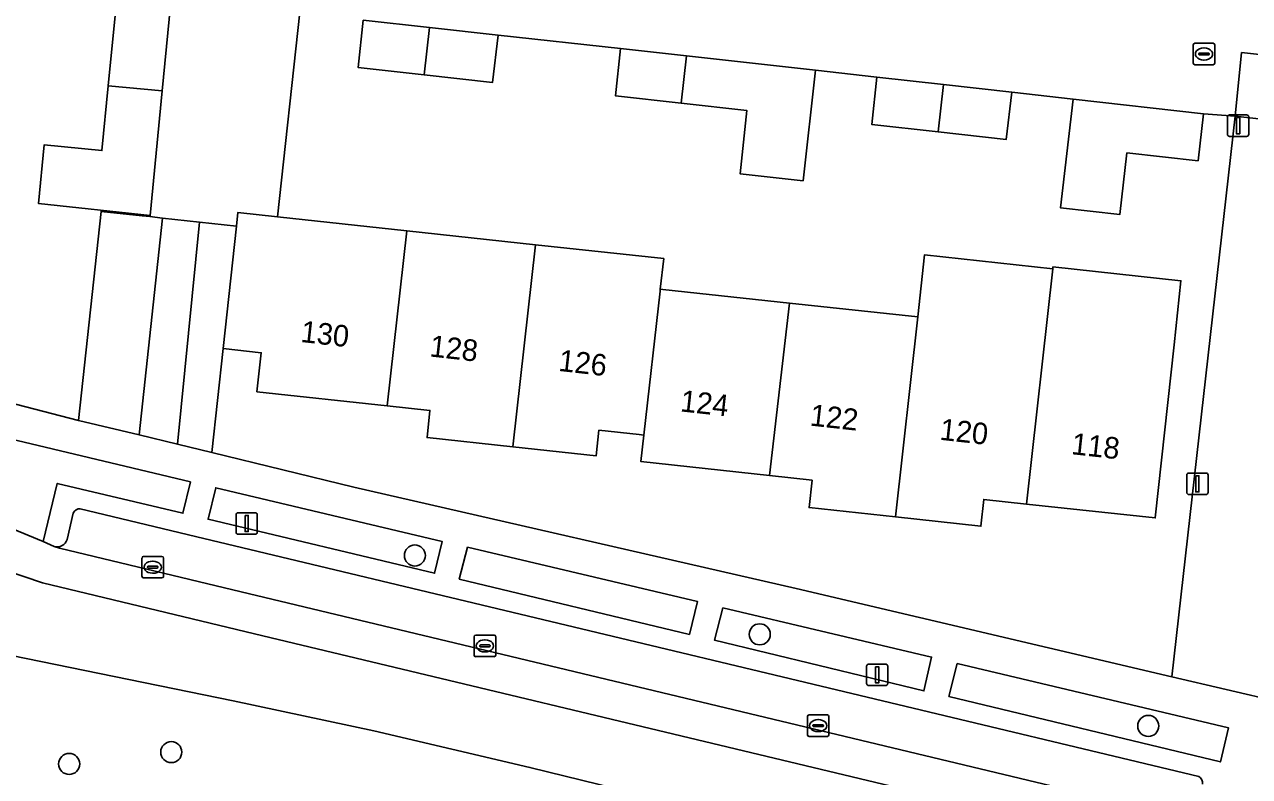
# Model space of a CAD drawing. Extents: x 162026 to 163502, y 387295 to 388169.
# Drawn here: x 162389.2 to 162446.1, y 387393.2 to 387428.2 of the extents above; entities that cross this region are included whole.
import ezdxf

# ---------------------------------------------------------------- set-up
doc = ezdxf.new("R2010")
doc.units = 0
for name, color, linetype in [('IMGEO_Berm_groen', 7, 'Continuous'), ('IMGEO_Boom', 7, 'Continuous'), ('IMGEO_Erf', 7, 'Continuous'), ('IMGEO_Groenvoorziening', 7, 'Continuous'), ('IMGEO_Kolk', 7, 'Continuous'), ('IMGEO_Lichtmast', 7, 'Continuous'), ('IMGEO_Muur', 7, 'Continuous'), ('IMGEO_Pand', 7, 'Continuous'), ('IMGEO_Pand_nummerreeks', 7, 'Continuous'), ('IMGEO_Parkeervlak_open', 7, 'Continuous'), ('IMGEO_Rijbaan_lokaal_gesloten', 7, 'Continuous'), ('IMGEO_Rijbaan_lokaal_open', 7, 'Continuous'), ('IMGEO_Voetpad_open', 7, 'Continuous')]:
    doc.layers.add(name, color=color, linetype=linetype)

msp = doc.modelspace()

# ---------------------------------------------------------------- linework, layer by layer
at = {"layer": 'IMGEO_Berm_groen'}
msp.add_lwpolyline([(162425.53, 387390.413), (162418.248, 387392.291), (162412.634, 387393.669), (162405.374, 387395.373), (162398.853, 387396.753), (162376.793, 387401.271)], dxfattribs=at)
at = {"layer": 'IMGEO_Boom'}
for centre in [(162407.286, 387403.51), (162423.306, 387399.849), (162441.353, 387395.594), (162395.972, 387394.379), (162391.229, 387393.829)]:
    msp.add_circle(centre, 0.489, dxfattribs=at)
at = {"layer": 'IMGEO_Erf'}
for points in [[(162386.331, 387411.152), (162391.662, 387409.78), (162392.713, 387419.492), (162394.616, 387419.286), (162394.98, 387419.247), (162394.985, 387419.298), (162389.801, 387419.859), (162390.065, 387422.578), (162392.75, 387422.317), (162393.042, 387425.325), (162393.359, 387428.586)], [(162401.939, 387428.743), (162400.911, 387419.241), (162406.912, 387418.59), (162412.884, 387417.942), (162418.844, 387417.296), (162418.685, 387415.884), (162418.808, 387415.871), (162424.683, 387415.234), (162430.645, 387414.587), (162430.965, 387417.474), (162436.918, 387416.828), (162436.927, 387416.912), (162442.872, 387416.267), (162442.549, 387413.295), (162441.676, 387405.253), (162435.704, 387405.901), (162433.715, 387406.117), (162433.58, 387404.87), (162429.615, 387405.3), (162425.601, 387405.735), (162425.739, 387407.005), (162423.767, 387407.219), (162417.783, 387407.869), (162417.922, 387409.102), (162417.71, 387409.125), (162415.833, 387409.328), (162415.703, 387408.133), (162411.84, 387408.552), (162407.851, 387408.985), (162407.988, 387410.246), (162406.001, 387410.462), (162399.952, 387411.118), (162400.149, 387412.928), (162398.38, 387413.12), (162397.856, 387408.293), (162404.454, 387406.677), (162424.994, 387401.97), (162442.45, 387397.88), (162445.392, 387423.92), (162443.92, 387424.02), (162443.67, 387421.84), (162440.363, 387422.209), (162440.026, 387419.339), (162437.269, 387419.663), (162437.861, 387424.709), (162435.01, 387425.03), (162434.76, 387422.83), (162431.598, 387423.184), (162428.51, 387423.53), (162428.75, 387425.72), (162425.89, 387426.044), (162425.318, 387420.914), (162422.396, 387421.242), (162422.709, 387424.176), (162419.657, 387424.518), (162416.6, 387424.86), (162416.84, 387427.05), (162411.15, 387427.68), (162410.9, 387425.48), (162407.724, 387425.836), (162404.65, 387426.18), (162404.89, 387428.37)]]:
    msp.add_lwpolyline(points, dxfattribs=at)
msp.add_lwpolyline([(162397.281, 387418.997), (162395.566, 387419.183), (162394.477, 387409.121), (162396.253, 387408.686)], close=True, dxfattribs=at)
at = {"layer": 'IMGEO_Groenvoorziening'}
msp.add_lwpolyline([(162383.903, 387406.679), (162390.026, 387404.153), (162390.673, 387406.855), (162396.508, 387405.474), (162396.863, 387406.924), (162380.357, 387410.869), (162380.357, 387410.999), (162378.049, 387411.538)], dxfattribs=at)
for points in [[(162398.035, 387406.657), (162397.682, 387405.194), (162408.2, 387402.685), (162408.554, 387404.163)], [(162409.73, 387403.895), (162409.347, 387402.412), (162420.036, 387399.843), (162420.417, 387401.368)], [(162421.591, 387401.072), (162421.21, 387399.574), (162430.935, 387397.221), (162431.286, 387398.789)], [(162432.469, 387398.487), (162432.092, 387396.966), (162444.703, 387393.926), (162445.078, 387395.51)]]:
    msp.add_lwpolyline(points, close=True, dxfattribs=at)
at = {"layer": 'IMGEO_Kolk'}
for p, q in [((162443.441, 387426.374), (162443.441, 387427.226)), ((162443.516, 387427.3), (162444.368, 387427.3)), ((162443.743, 387426.843), (162444.141, 387426.843)), ((162443.929, 387427.08), (162443.954, 387427.08)), ((162444.442, 387427.226), (162444.442, 387426.374)), ((162444.368, 387426.3), (162443.516, 387426.3)), ((162443.7, 387426.794), (162443.7, 387426.806)), ((162444.138, 387426.757), (162443.74, 387426.757)), ((162443.952, 387426.52), (162443.927, 387426.52)), ((162444.184, 387426.806), (162444.184, 387426.794)), ((162394.611, 387402.541), (162394.611, 387403.393)), ((162394.686, 387403.467), (162395.538, 387403.467)), ((162394.87, 387402.961), (162394.87, 387402.973)), ((162394.913, 387403.01), (162395.311, 387403.01)), ((162395.099, 387403.247), (162395.124, 387403.247)), ((162395.354, 387402.973), (162395.354, 387402.961)), ((162395.612, 387403.393), (162395.612, 387402.541)), ((162395.538, 387402.467), (162394.686, 387402.467)), ((162395.308, 387402.924), (162394.91, 387402.924)), ((162395.122, 387402.687), (162395.097, 387402.687)), ((162410.039, 387398.886), (162410.039, 387399.738)), ((162410.114, 387399.812), (162410.966, 387399.812)), ((162410.527, 387399.592), (162410.552, 387399.592)), ((162411.04, 387399.738), (162411.04, 387398.886)), ((162410.298, 387399.306), (162410.298, 387399.318)), ((162410.736, 387399.269), (162410.338, 387399.269)), ((162410.341, 387399.355), (162410.739, 387399.355)), ((162410.55, 387399.032), (162410.525, 387399.032)), ((162410.782, 387399.318), (162410.782, 387399.306)), ((162410.966, 387398.812), (162410.114, 387398.812)), ((162425.595, 387396.109), (162426.447, 387396.109)), ((162425.52, 387395.183), (162425.52, 387396.035)), ((162425.779, 387395.603), (162425.779, 387395.615)), ((162426.217, 387395.566), (162425.819, 387395.566)), ((162425.822, 387395.652), (162426.22, 387395.652)), ((162426.008, 387395.889), (162426.033, 387395.889)), ((162426.263, 387395.615), (162426.263, 387395.603)), ((162426.521, 387396.035), (162426.521, 387395.183)), ((162426.447, 387395.109), (162425.595, 387395.109)), ((162426.031, 387395.329), (162426.006, 387395.329))]:
    msp.add_line(p, q, dxfattribs=at)
for points in [[(162443.441, 387426.374), (162443.441, 387427.226)], [(162443.516, 387427.3), (162444.368, 387427.3)], [(162444.442, 387427.226), (162444.442, 387426.374)], [(162444.368, 387426.3), (162443.516, 387426.3)], [(162394.611, 387402.541), (162394.611, 387403.393)], [(162394.686, 387403.467), (162395.538, 387403.467)], [(162395.612, 387403.393), (162395.612, 387402.541)], [(162395.538, 387402.467), (162394.686, 387402.467)], [(162410.039, 387398.886), (162410.039, 387399.738)], [(162410.114, 387399.812), (162410.966, 387399.812)], [(162411.04, 387399.738), (162411.04, 387398.886)], [(162410.966, 387398.812), (162410.114, 387398.812)], [(162425.595, 387396.109), (162426.447, 387396.109)], [(162425.52, 387395.183), (162425.52, 387396.035)], [(162426.521, 387396.035), (162426.521, 387395.183)], [(162426.447, 387395.109), (162425.595, 387395.109)]]:
    msp.add_lwpolyline(points, dxfattribs=at)
for centre, radius, start, end in [((162443.518, 387427.224), 0.0765, 91.552, 178.448), ((162443.518, 387427.224), 0.0765, 91.552, 178.448), ((162443.74, 387426.803), 0.0403, 85.8775, 175.7526), ((162444.145, 387426.805), 0.0386, 1.7309, 96.639), ((162444.366, 387427.224), 0.0765, 1.552, 88.448), ((162444.366, 387427.224), 0.0765, 1.552, 88.448), ((162443.518, 387426.376), 0.0765, 181.552, 268.448), ((162443.518, 387426.376), 0.0765, 181.552, 268.448), ((162443.737, 387426.793), 0.0366, 178.938, 274.7102), ((162444.141, 387426.8), 0.043, 264.8664, 352.4533), ((162444.366, 387426.376), 0.0765, 271.552, 358.448), ((162444.366, 387426.376), 0.0765, 271.552, 358.448), ((162394.688, 387403.391), 0.0765, 91.552, 178.448), ((162394.688, 387403.391), 0.0765, 91.552, 178.448), ((162394.91, 387402.97), 0.0403, 85.8775, 175.7526), ((162394.907, 387402.96), 0.0366, 178.938, 274.7102), ((162395.311, 387402.967), 0.043, 264.8664, 352.4533), ((162395.315, 387402.972), 0.0386, 1.7309, 96.639), ((162395.536, 387403.391), 0.0765, 1.552, 88.448), ((162395.536, 387403.391), 0.0765, 1.552, 88.448), ((162394.688, 387402.543), 0.0765, 181.552, 268.448), ((162394.688, 387402.543), 0.0765, 181.552, 268.448), ((162395.536, 387402.543), 0.0765, 271.552, 358.448), ((162395.536, 387402.543), 0.0765, 271.552, 358.448), ((162410.116, 387399.736), 0.0765, 91.552, 178.448), ((162410.116, 387399.736), 0.0765, 91.552, 178.448), ((162410.964, 387399.736), 0.0765, 1.552, 88.448), ((162410.964, 387399.736), 0.0765, 1.552, 88.448), ((162410.338, 387399.315), 0.0403, 85.8775, 175.7526), ((162410.335, 387399.305), 0.0366, 178.938, 274.7102), ((162410.739, 387399.312), 0.043, 264.8664, 352.4533), ((162410.743, 387399.317), 0.0386, 1.7309, 96.639), ((162410.116, 387398.888), 0.0765, 181.552, 268.448), ((162410.116, 387398.888), 0.0765, 181.552, 268.448), ((162410.964, 387398.888), 0.0765, 271.552, 358.448), ((162410.964, 387398.888), 0.0765, 271.552, 358.448), ((162425.597, 387396.033), 0.0765, 91.552, 178.448), ((162425.597, 387396.033), 0.0765, 91.552, 178.448), ((162426.445, 387396.033), 0.0765, 1.552, 88.448), ((162426.445, 387396.033), 0.0765, 1.552, 88.448), ((162425.819, 387395.612), 0.0403, 85.8775, 175.7526), ((162425.816, 387395.602), 0.0366, 178.938, 274.7102), ((162426.22, 387395.609), 0.043, 264.8664, 352.4533), ((162426.224, 387395.614), 0.0386, 1.7309, 96.639), ((162425.597, 387395.185), 0.0765, 181.552, 268.448), ((162425.597, 387395.185), 0.0765, 181.552, 268.448), ((162426.445, 387395.185), 0.0765, 271.552, 358.448), ((162426.445, 387395.185), 0.0765, 271.552, 358.448)]:
    msp.add_arc(centre, radius, start, end, dxfattribs=at)
for centre, major_axis, ratio, start_param, end_param in [((162443.928, 387426.8), (-0.387, 0.002), 0.722429, 4.712389, 7.853982), ((162443.953, 387426.8), (-0.39, 0.002), 0.717154, 1.570796, 4.712389), ((162395.098, 387402.967), (-0.387, 0.002), 0.722429, 4.712389, 7.853982), ((162395.123, 387402.967), (-0.39, 0.002), 0.717154, 1.570796, 4.712389), ((162410.526, 387399.312), (-0.387, 0.002), 0.722429, 4.712389, 7.853982), ((162410.551, 387399.312), (-0.39, 0.002), 0.717154, 1.570796, 4.712389), ((162426.007, 387395.609), (-0.387, 0.002), 0.722429, 4.712389, 7.853982), ((162426.032, 387395.609), (-0.39, 0.002), 0.717154, 1.570796, 4.712389)]:
    msp.add_ellipse(centre, major_axis=major_axis, ratio=ratio, start_param=start_param, end_param=end_param, dxfattribs=at)
at = {"layer": 'IMGEO_Lichtmast'}
for p, q in [((162445.031, 387423.072), (162445.031, 387423.872)), ((162445.031, 387423.872), (162445.031, 387423.072)), ((162445.131, 387423.972), (162445.921, 387423.972)), ((162445.921, 387423.972), (162445.131, 387423.972)), ((162446.021, 387423.872), (162446.021, 387423.072)), ((162446.021, 387423.072), (162446.021, 387423.872)), ((162445.921, 387422.972), (162445.131, 387422.972)), ((162445.131, 387422.972), (162445.921, 387422.972)), ((162443.139, 387406.441), (162443.139, 387407.241)), ((162443.139, 387407.241), (162443.139, 387406.441)), ((162443.239, 387407.341), (162444.029, 387407.341)), ((162444.029, 387407.341), (162443.239, 387407.341)), ((162444.129, 387407.241), (162444.129, 387406.441)), ((162444.129, 387406.441), (162444.129, 387407.241)), ((162444.029, 387406.341), (162443.239, 387406.341)), ((162443.239, 387406.341), (162444.029, 387406.341)), ((162398.978, 387404.597), (162398.978, 387405.397)), ((162398.978, 387405.397), (162398.978, 387404.597)), ((162399.078, 387405.497), (162399.868, 387405.497)), ((162399.868, 387405.497), (162399.078, 387405.497)), ((162399.968, 387405.397), (162399.968, 387404.597)), ((162399.968, 387404.597), (162399.968, 387405.397)), ((162399.868, 387404.497), (162399.078, 387404.497)), ((162399.078, 387404.497), (162399.868, 387404.497)), ((162428.365, 387398.468), (162429.155, 387398.468)), ((162429.155, 387398.468), (162428.365, 387398.468)), ((162428.265, 387397.568), (162428.265, 387398.368)), ((162428.265, 387398.368), (162428.265, 387397.568)), ((162429.255, 387398.368), (162429.255, 387397.568)), ((162429.255, 387397.568), (162429.255, 387398.368)), ((162429.155, 387397.468), (162428.365, 387397.468)), ((162428.365, 387397.468), (162429.155, 387397.468))]:
    msp.add_line(p, q, dxfattribs=at)
for points in [[(162445.451, 387423.847), (162445.601, 387423.847), (162445.601, 387423.097), (162445.451, 387423.097), (162445.451, 387423.847)], [(162443.559, 387407.216), (162443.709, 387407.216), (162443.709, 387406.466), (162443.559, 387406.466), (162443.559, 387407.216)], [(162399.398, 387405.372), (162399.548, 387405.372), (162399.548, 387404.622), (162399.398, 387404.622), (162399.398, 387405.372)], [(162428.685, 387398.343), (162428.835, 387398.343), (162428.835, 387397.593), (162428.685, 387397.593), (162428.685, 387398.343)]]:
    msp.add_lwpolyline(points, dxfattribs=at)
for centre, start, end in [((162445.131, 387423.872), 90, 180), ((162445.131, 387423.872), 90, 180), ((162445.921, 387423.872), 0, 90), ((162445.921, 387423.872), 360, 90), ((162445.131, 387423.072), 180, 270), ((162445.131, 387423.072), 180, 270), ((162445.921, 387423.072), 270, 0), ((162445.921, 387423.072), 270, 0), ((162443.239, 387407.241), 90, 180), ((162443.239, 387407.241), 90, 180), ((162444.029, 387407.241), 0, 90), ((162444.029, 387407.241), 360, 90), ((162443.239, 387406.441), 180, 270), ((162443.239, 387406.441), 180, 270), ((162444.029, 387406.441), 270, 0), ((162444.029, 387406.441), 270, 0), ((162399.078, 387405.397), 90, 180), ((162399.078, 387405.397), 90, 180), ((162399.868, 387405.397), 0, 90), ((162399.868, 387405.397), 360, 90), ((162399.078, 387404.597), 180, 270), ((162399.078, 387404.597), 180, 270), ((162399.868, 387404.597), 270, 0), ((162399.868, 387404.597), 270, 0), ((162428.365, 387398.368), 90, 180), ((162428.365, 387398.368), 90, 180), ((162429.155, 387398.368), 0, 90), ((162429.155, 387398.368), 360, 90), ((162428.365, 387397.568), 180, 270), ((162428.365, 387397.568), 180, 270), ((162429.155, 387397.568), 270, 0), ((162429.155, 387397.568), 270, 0)]:
    msp.add_arc(centre, 0.1, start, end, dxfattribs=at)
at = {"layer": 'IMGEO_Muur'}
for points in [[(162443.92, 387424.02), (162445.392, 387423.92)], [(162445.392, 387423.92), (162442.45, 387397.88)], [(162391.662, 387409.78), (162386.331, 387411.152)]]:
    msp.add_lwpolyline(points, dxfattribs=at)
at = {"layer": 'IMGEO_Pand'}
for points in [[(162396.134, 387431.128), (162391.126, 387431.615), (162390.855, 387428.829), (162393.359, 387428.586), (162393.042, 387425.325), (162395.547, 387425.082)], [(162404.89, 387428.37), (162404.65, 387426.18), (162407.724, 387425.836), (162407.97, 387428.03)], [(162407.97, 387428.03), (162407.724, 387425.836), (162410.9, 387425.48), (162411.15, 387427.68)], [(162416.84, 387427.05), (162416.6, 387424.86), (162419.657, 387424.518), (162419.904, 387426.712)], [(162425.89, 387426.044), (162419.904, 387426.712), (162419.657, 387424.518), (162422.709, 387424.176), (162422.396, 387421.242), (162425.318, 387420.914)], [(162428.75, 387425.72), (162428.51, 387423.53), (162431.598, 387423.184), (162431.842, 387425.379)], [(162395.547, 387425.082), (162393.042, 387425.325), (162392.75, 387422.317), (162390.065, 387422.578), (162389.801, 387419.859), (162394.985, 387419.298)], [(162431.842, 387425.379), (162431.598, 387423.184), (162434.76, 387422.83), (162435.01, 387425.03)], [(162443.92, 387424.02), (162437.861, 387424.709), (162437.269, 387419.663), (162440.026, 387419.339), (162440.363, 387422.209), (162443.67, 387421.84)], [(162395.566, 387419.183), (162394.98, 387419.247), (162394.616, 387419.286), (162392.713, 387419.492), (162391.662, 387409.78), (162394.477, 387409.121)], [(162406.912, 387418.59), (162400.911, 387419.241), (162399.064, 387419.442), (162398.996, 387418.812), (162398.38, 387413.12), (162400.149, 387412.928), (162399.952, 387411.118), (162406.001, 387410.462)], [(162406.001, 387410.462), (162407.988, 387410.246), (162407.851, 387408.985), (162411.84, 387408.552), (162412.884, 387417.942), (162406.912, 387418.59)], [(162418.685, 387415.884), (162418.844, 387417.296), (162412.884, 387417.942), (162411.84, 387408.552), (162415.703, 387408.133), (162415.833, 387409.328), (162417.71, 387409.125), (162417.922, 387409.102), (162418.674, 387415.784)], [(162436.918, 387416.828), (162430.965, 387417.474), (162430.645, 387414.587), (162429.615, 387405.3), (162433.58, 387404.87), (162433.715, 387406.117), (162435.704, 387405.901)], [(162442.549, 387413.295), (162442.872, 387416.267), (162436.927, 387416.912), (162436.918, 387416.828), (162435.704, 387405.901), (162441.676, 387405.253)], [(162424.683, 387415.234), (162418.808, 387415.871), (162418.685, 387415.884), (162418.674, 387415.784), (162417.922, 387409.102), (162417.783, 387407.869), (162423.767, 387407.219)], [(162430.645, 387414.587), (162424.683, 387415.234), (162423.767, 387407.219), (162425.739, 387407.005), (162425.601, 387405.735), (162429.615, 387405.3)]]:
    msp.add_lwpolyline(points, close=True, dxfattribs=at)
at = {"layer": 'IMGEO_Parkeervlak_open'}
msp.add_lwpolyline([(162442.45, 387397.88), (162447.498, 387396.697), (162450.443, 387423.342), (162445.392, 387423.92)], close=True, dxfattribs=at)
for points in [[(162391.421, 387405.479), (162391.131, 387404.256)], [(162397.49, 387404.3), (162391.744, 387405.681)], [(162443.695, 387393.247), (162397.49, 387404.3)], [(162390.534, 387403.927), (162390.78, 387403.852), (162398.449, 387402.001), (162443.887, 387391.121)]]:
    msp.add_lwpolyline(points, dxfattribs=at)
for centre, radius, start, end in [((162391.728, 387405.347), 0.334, 87.3036, 156.739), ((162390.662, 387404.401), 0.491, 254.9237, 342.7936), ((162443.547, 387392.952), 0.33, 349.0878, 63.3985)]:
    msp.add_arc(centre, radius, start, end, dxfattribs=at)
at = {"layer": 'IMGEO_Rijbaan_lokaal_gesloten'}
for points in [[(162381.722, 387407.605), (162380.574, 387405.433), (162389.995, 387402.241), (162400.227, 387399.776), (162452.771, 387387.216), (162481.027, 387380.405)], [(162453.238, 387388.898), (162452.182, 387389.149), (162444.366, 387391.024), (162443.887, 387391.121), (162398.449, 387402.001), (162390.78, 387403.852), (162390.534, 387403.927), (162390.026, 387404.153), (162383.903, 387406.679)]]:
    msp.add_lwpolyline(points, dxfattribs=at)
at = {"layer": 'IMGEO_Rijbaan_lokaal_open'}
for points in [[(162396.134, 387431.128), (162395.547, 387425.082), (162394.985, 387419.298), (162394.98, 387419.247), (162395.566, 387419.183), (162397.281, 387418.997), (162398.996, 387418.812), (162399.064, 387419.442), (162400.911, 387419.241), (162401.939, 387428.743)], [(162404.89, 387428.37), (162407.97, 387428.03), (162411.15, 387427.68), (162416.84, 387427.05), (162419.904, 387426.712), (162425.89, 387426.044), (162428.75, 387425.72), (162431.842, 387425.379), (162435.01, 387425.03), (162437.861, 387424.709), (162443.92, 387424.02), (162445.392, 387423.92), (162445.691, 387426.865), (162456.91, 387425.623)], [(162379.984, 387404.638), (162377.378, 387405.275), (162376.52, 387401.378), (162376.494, 387401.259), (162376.793, 387401.271), (162398.853, 387396.753), (162405.374, 387395.373), (162412.634, 387393.669), (162418.248, 387392.291), (162425.53, 387390.413)], [(162481.027, 387380.405), (162452.771, 387387.216), (162400.227, 387399.776), (162389.995, 387402.241), (162380.574, 387405.433)]]:
    msp.add_lwpolyline(points, dxfattribs=at)
msp.add_lwpolyline([(162456.567, 387422.641), (162456.91, 387425.623), (162445.691, 387426.865), (162445.392, 387423.92), (162450.443, 387423.342)], close=True, dxfattribs=at)
at = {"layer": 'IMGEO_Voetpad_open'}
for points in [[(162398.38, 387413.12), (162398.996, 387418.812), (162397.281, 387418.997), (162396.253, 387408.686), (162397.856, 387408.293)], [(162408.2, 387402.685), (162397.682, 387405.194), (162398.035, 387406.657), (162408.554, 387404.163)], [(162409.73, 387403.895), (162420.417, 387401.368), (162420.036, 387399.843), (162409.347, 387402.412)], [(162421.591, 387401.072), (162431.286, 387398.789), (162430.935, 387397.221), (162421.21, 387399.574)], [(162432.469, 387398.487), (162445.078, 387395.51), (162444.703, 387393.926), (162432.092, 387396.966)]]:
    msp.add_lwpolyline(points, close=True, dxfattribs=at)
for points in [[(162452.941, 387395.422), (162447.498, 387396.697), (162442.45, 387397.88), (162424.994, 387401.97), (162404.454, 387406.677), (162397.856, 387408.293), (162396.253, 387408.686), (162394.477, 387409.121), (162391.662, 387409.78), (162386.331, 387411.152), (162377.809, 387413.191), (162373.56, 387414.003), (162373.616, 387414.217), (162371.957, 387414.634), (162371.947, 387414.533)], [(162372.429, 387410.931), (162375.368, 387410.356), (162377.495, 387409.656), (162378.049, 387411.538), (162380.357, 387410.999), (162380.357, 387410.869), (162396.863, 387406.924), (162396.508, 387405.474), (162390.673, 387406.855), (162390.026, 387404.153), (162390.534, 387403.927)], [(162391.131, 387404.256), (162391.421, 387405.479)], [(162391.744, 387405.681), (162397.49, 387404.3), (162443.695, 387393.247)]]:
    msp.add_lwpolyline(points, dxfattribs=at)
for centre, radius, start, end in [((162391.728, 387405.347), 0.334, 87.3036, 156.739), ((162390.662, 387404.401), 0.491, 254.9237, 342.7936), ((162443.547, 387392.952), 0.33, 349.0878, 63.3985)]:
    msp.add_arc(centre, radius, start, end, dxfattribs=at)

# ---------------------------------------------------------------- texts
at = {"layer": 'IMGEO_Pand_nummerreeks'}
for s, rotation, p in [('130', 353.6001, (162401.952, 387413.43)), ('128', 353.5992, (162407.942, 387412.758)), ('126', 353.6001, (162413.928, 387412.086)), ('124', 353.7548, (162419.583, 387410.206)), ('122', 353.7532, (162425.606, 387409.547)), ('120', 353.7548, (162431.637, 387408.887)), ('118', 353.7548, (162437.751, 387408.218))]:
    msp.add_text(s, height=1, rotation=rotation, dxfattribs=at).set_placement(p)

doc.saveas('drawing.dxf')
